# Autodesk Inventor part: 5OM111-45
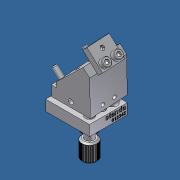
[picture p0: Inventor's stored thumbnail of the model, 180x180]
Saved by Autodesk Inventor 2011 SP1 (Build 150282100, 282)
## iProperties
Created: 2011-06
Part Number: 5OM111-45
Document SubType Name: Modeling
Designer: Darius
Density: 1 g/cm^3
Author: Darius
Translation Standard: STEP AP203
FileName: 5OM111-45.STEP
PreProcessor: SolidWorks 2003240
PostProcessor: Build: 282, Release: 2011 SP1 - Date: Thu 08/05/2010
Sent Units: millimeter
Uncertainty: 1e-05
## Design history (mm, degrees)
feature "Base1"
node "NONE"
